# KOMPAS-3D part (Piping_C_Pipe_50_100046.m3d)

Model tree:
1. Plane XY
2. Plane ZX
3. Plane ZY
4. X Axis
5. Y Axis
6. Z Axis
7. Origin
8. Path  (labels: Труба Dy 50; Тройник Dy 50)
9. Plane of section
10. Section of pipe
11. Pipe
     Толщина стенки 1 = 1

Referenced files in C:\Program Files\ASCON\KOMPAS-3D V10\Libs\Piping\Models\Tanks\: Tanks.a3d
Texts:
  Pipe Dn 50
  Steel ASTM A295
  Three Point Plane
  Plane at Angle
  Line and Point Plane
  Axis through Two Vertices
  Axis of Feature
  Axis of Conical Surface
  Axis through Edge
  Приклеить элемент выдавливания
  Приклеить элемент вращения
  Приклеить кинематический элемент
  Приклеить элемент по сечениям
  Trim by Surface
  Trim by Sketch
  Feature with No History
  Intersection Axis of Two Planes
  Two Line Plane
  Line and Face Plane
  Bend by line
  Hole in sheet body
  Cut in sheet body
  Point in CM
  Linear Dimension from Line to Point
  Surface Finish Symbol
  Geometric Tolerance Symbol
  Текст на чертеже
  Линия-выноска #1
  Линия-выноска #2
  Линия-выноска #3
  Отклонения формы и база
  Марка координационной оси
  Марка/позиционное обозначение с линией-выноской
  Марка/позиционное обозначение на линии
  Марка/позиционное обозначение без линии-выноски
  Труба Dy 50
  Тройник Dy 50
